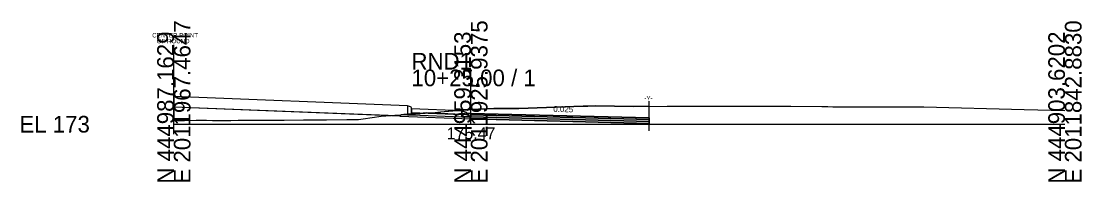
# Model space of a CAD drawing. Extents: x -26 to 153, y -10 to 6017.
# Drawn here: x -25.7 to 152.8, y 490.3 to 517.3 of the extents above; entities that cross this region are included whole.
import ezdxf

# ---------------------------------------------------------------- set-up
doc = ezdxf.new("R2010")
doc.units = 0
for name, color, linetype in [('Exist Cross Section Cell', 7, 'Continuous'), ('Exist XS Ground Line', 7, 'Continuous'), ('Prop CMT Conc Surface', 7, 'Continuous'), ('Prop CMT Concrete Structures', 7, 'Continuous'), ('Prop CMT Pvmt Course 1', 7, 'Continuous'), ('Prop CMT Pvmt Course 1 CG', 7, 'Continuous'), ('Prop CMT Pvmt Course 2', 7, 'Continuous'), ('Prop CMT Pvmt Course 3', 7, 'Continuous'), ('Prop CMT Pvmt Surface', 7, 'Continuous'), ('Prop CMT Shear Line', 7, 'Continuous'), ('Prop CMT Shear Line Text', 7, 'Continuous'), ('Prop CMT Slope Grass', 7, 'Continuous'), ('Prop CMT Subgrade Earthwork', 7, 'Continuous'), ('Prop XS Earthwork Shape', 7, 'Continuous'), ('Prop XS SE Text', 7, 'Continuous')]:
    doc.layers.add(name, color=color, linetype=linetype)

msp = doc.modelspace()

# ---------------------------------------------------------------- linework, layer by layer
at = {"layer": 'Exist Cross Section Cell'}
for p, q in [((50, 500), (50, 509.2)), ((0, 500), (50, 500)), ((50, 500), (150, 500))]:
    msp.add_line(p, q, dxfattribs=at)
at = {"layer": 'Exist XS Ground Line'}
msp.add_lwpolyline([(0, 500.62), (0.54, 500.63), (1.82, 500.64), (3.76, 500.67), (4.41, 500.67), (5.51, 500.66), (6.5, 500.65), (7.23, 500.64), (8.25, 500.63), (9.05, 500.64), (9.58, 500.65), (10.84, 500.67), (12.73, 500.69), (15.59, 500.68), (17.25, 500.67), (18.59, 500.69), (21.8, 500.74), (22.46, 500.74), (22.97, 500.74), (23.91, 500.74), (24.72, 500.74), (25.22, 500.74), (25.69, 500.72), (29.1, 500.78), (31.11, 500.8), (31.88, 500.89), (34.88, 501.35), (35.67, 501.41), (44.01, 501.99), (44.9, 502.08), (47.71, 502.3), (48.49, 502.43), (49.32, 502.44), (50, 502.47), (53.89, 502.65), (58.09, 502.65), (68.9, 503.03), (69.68, 503.04), (71, 503.07), (77.4, 502.98), (83.04, 503.05), (87.07, 503.06), (95.08, 503.04), (96.79, 503.04), (97.23, 503.03), (103.87, 503.01), (109.1, 502.98), (110.07, 502.97), (110.93, 502.93), (114.75, 502.94), (123.21, 502.94), (126.24, 502.92), (143.16, 502.45), (150, 502.32)], dxfattribs=at)
at = {"layer": 'Prop CMT Conc Surface'}
for points in [[(40, 502.76), (39.96, 502.87), (39.85, 502.91), (39.34, 503.1)], [(40, 502.6), (40, 502.76)], [(50, 501.8), (49.25, 501.82), (49.25, 501.99), (48.5, 502.24)]]:
    msp.add_lwpolyline(points, dxfattribs=at)
at = {"layer": 'Prop CMT Concrete Structures'}
for points in [[(40, 502.76), (39.96, 502.87), (39.85, 502.91), (39.34, 503.1)], [(39.34, 503.1), (39.34, 501.6)], [(40, 502.6), (40, 502.76)], [(40, 501.6), (40, 502.6)], [(40, 502.6), (40, 502.01)], [(48.5, 502.24), (40, 502.58)], [(40, 501.99), (48.5, 501.65)], [(50, 501.8), (49.25, 501.82), (49.25, 501.99), (48.5, 502.24)], [(48.5, 502.24), (48.5, 501.26)], [(48.5, 501.65), (48.5, 502.24)], [(50, 501.22), (50, 501.8)], [(39.34, 501.6), (40, 501.6)], [(48.5, 501.26), (50, 501.22)]]:
    msp.add_lwpolyline(points, dxfattribs=at)
at = {"layer": 'Prop CMT Pvmt Course 1'}
for points in [[(50, 501.8), (80, 501.05)], [(50, 501.55), (50, 501.8)], [(80, 500.8), (50, 501.55)], [(80, 501.05), (80, 500.8)]]:
    msp.add_lwpolyline(points, dxfattribs=at)
msp.add_lwpolyline([(50, 501.55), (50, 501.68), (50, 501.68), (50, 501.55)], close=True, dxfattribs=at)
at = {"layer": 'Prop CMT Pvmt Course 1 CG'}
for points in [[(50, 500.88), (50, 501.22)], [(80, 500.13), (80, 500.46)]]:
    msp.add_lwpolyline(points, dxfattribs=at)
at = {"layer": 'Prop CMT Pvmt Course 2'}
for points in [[(50, 501.22), (50, 501.55)], [(50, 501.55), (80, 500.8)], [(80, 500.46), (50, 501.22)], [(80, 500.8), (80, 500.46)]]:
    msp.add_lwpolyline(points, dxfattribs=at)
at = {"layer": 'Prop CMT Pvmt Course 3'}
for points in [[(40, 501.6), (48.5, 501.26)], [(50, 501.22), (80, 500.46)], [(50, 500.88), (50, 501.22)], [(80, 500.13), (50, 500.88)], [(80, 500.46), (80, 500.13)]]:
    msp.add_lwpolyline(points, dxfattribs=at)
at = {"layer": 'Prop CMT Pvmt Surface'}
msp.add_lwpolyline([(50, 501.8), (80, 501.05)], dxfattribs=at)
at = {"layer": 'Prop CMT Shear Line'}
for p, q in [((0, 498.34), (0, 513.34)), ((80, 498.87), (80, 503.89))]:
    msp.add_line(p, q, dxfattribs=at)
at = {"layer": 'Prop CMT Slope Grass'}
for p, q in [((39.34, 503.08), (0, 504.65)), ((38.06, 501.36), (0, 502.88))]:
    msp.add_line(p, q, dxfattribs=at)
at = {"layer": 'Prop CMT Subgrade Earthwork'}
for p, q in [((0, 504.65), (0, 500.62)), ((80, 500.13), (80, 503.01)), ((38.34, 501.64), (38.06, 501.36))]:
    msp.add_line(p, q, dxfattribs=at)
for points in [[(38.06, 501.36), (50, 500.88)], [(38.34, 501.64), (39.34, 501.6)], [(50, 500.88), (80, 500.13)]]:
    msp.add_lwpolyline(points, dxfattribs=at)
at = {"layer": 'Prop XS Earthwork Shape'}
for points in [[(6.5, 500.65), (7.23, 500.64), (8.25, 500.63), (9.05, 500.64), (9.58, 500.65), (10.84, 500.67), (12.73, 500.69), (15.59, 500.68), (17.25, 500.67), (18.59, 500.69), (21.8, 500.74), (22.46, 500.74), (22.97, 500.74), (23.91, 500.74), (24.72, 500.74), (25.22, 500.74), (25.69, 500.72), (29.1, 500.78), (31.11, 500.8), (31.88, 500.89), (34.88, 501.35), (35.67, 501.41), (36.08, 501.44), (0, 502.88), (0, 500.62), (0.54, 500.63), (1.82, 500.64), (3.76, 500.67), (4.41, 500.67), (5.51, 500.66)], [(80, 500.13), (80, 501.05), (50, 501.8), (50, 501.22), (48.5, 501.26), (48.5, 501.65), (42.56, 501.89), (40, 501.71), (40, 501.6), (39.34, 501.6), (38.69, 501.62), (38.29, 501.6), (38.06, 501.36), (50, 500.88)], [(39.34, 501.67), (39.34, 501.6), (40, 501.6), (40, 501.71)], [(44.9, 502.08), (47.44, 502.28), (48.5, 502.24), (48.5, 501.65), (42.56, 501.89), (44.01, 501.99)], [(80, 501.05), (80, 503.01), (77.4, 502.98), (71, 503.07), (69.68, 503.04), (68.9, 503.03), (58.09, 502.65), (53.89, 502.65), (50, 502.47), (49.32, 502.44), (48.49, 502.43), (47.71, 502.3), (47.44, 502.28), (48.5, 502.24), (49.25, 501.99), (49.25, 501.82), (50, 501.8)], [(50, 501.22), (50, 501.8), (49.25, 501.82), (49.25, 501.99), (48.5, 502.24), (48.5, 501.65), (48.5, 501.26)], [(38.06, 501.36), (36.08, 501.44), (38.29, 501.6)], [(38.69, 501.62), (39.34, 501.6), (39.34, 501.67)]]:
    msp.add_lwpolyline(points, close=True, dxfattribs=at)

# ---------------------------------------------------------------- texts
at = {"layer": 'Exist Cross Section Cell'}
for s, p in [('E 2011967.4647', (2.8, 490)), ('E 2011925.9375', (52.8, 490)), ('E 2011842.8830', (152.8, 490)), ('N 444987.1629', (0, 490)), ('N 444959.3153', (50, 490)), ('N 444903.6202', (150, 490))]:
    msp.add_text(s, height=2.8, rotation=90, dxfattribs=at).set_placement(p)
for s, p in [('RND1', (40, 509.2)), ('10+25.00 / 1', (40, 506.4)), ('EL 173', (-26, 498.6))]:
    msp.add_text(s, height=2.8, dxfattribs=at).set_placement(p)
at = {"layer": 'Exist XS Ground Line'}
msp.add_text('175.47', height=2, dxfattribs=at).set_placement((45.94, 497.47))
at = {"layer": 'Prop CMT Shear Line Text'}
for s, p in [('CENTER POINT', (-3.64, 514.6)), ('OF ROUND', (-2.88, 513.62)), ('-Y-', (79.21, 504))]:
    msp.add_text(s, height=0.75, dxfattribs=at).set_placement(p)
at = {"layer": 'Prop XS SE Text'}
msp.add_text('0.025', height=1, rotation=358.5613, dxfattribs=at).set_placement((63.87, 502.08))

doc.saveas('drawing.dxf')
